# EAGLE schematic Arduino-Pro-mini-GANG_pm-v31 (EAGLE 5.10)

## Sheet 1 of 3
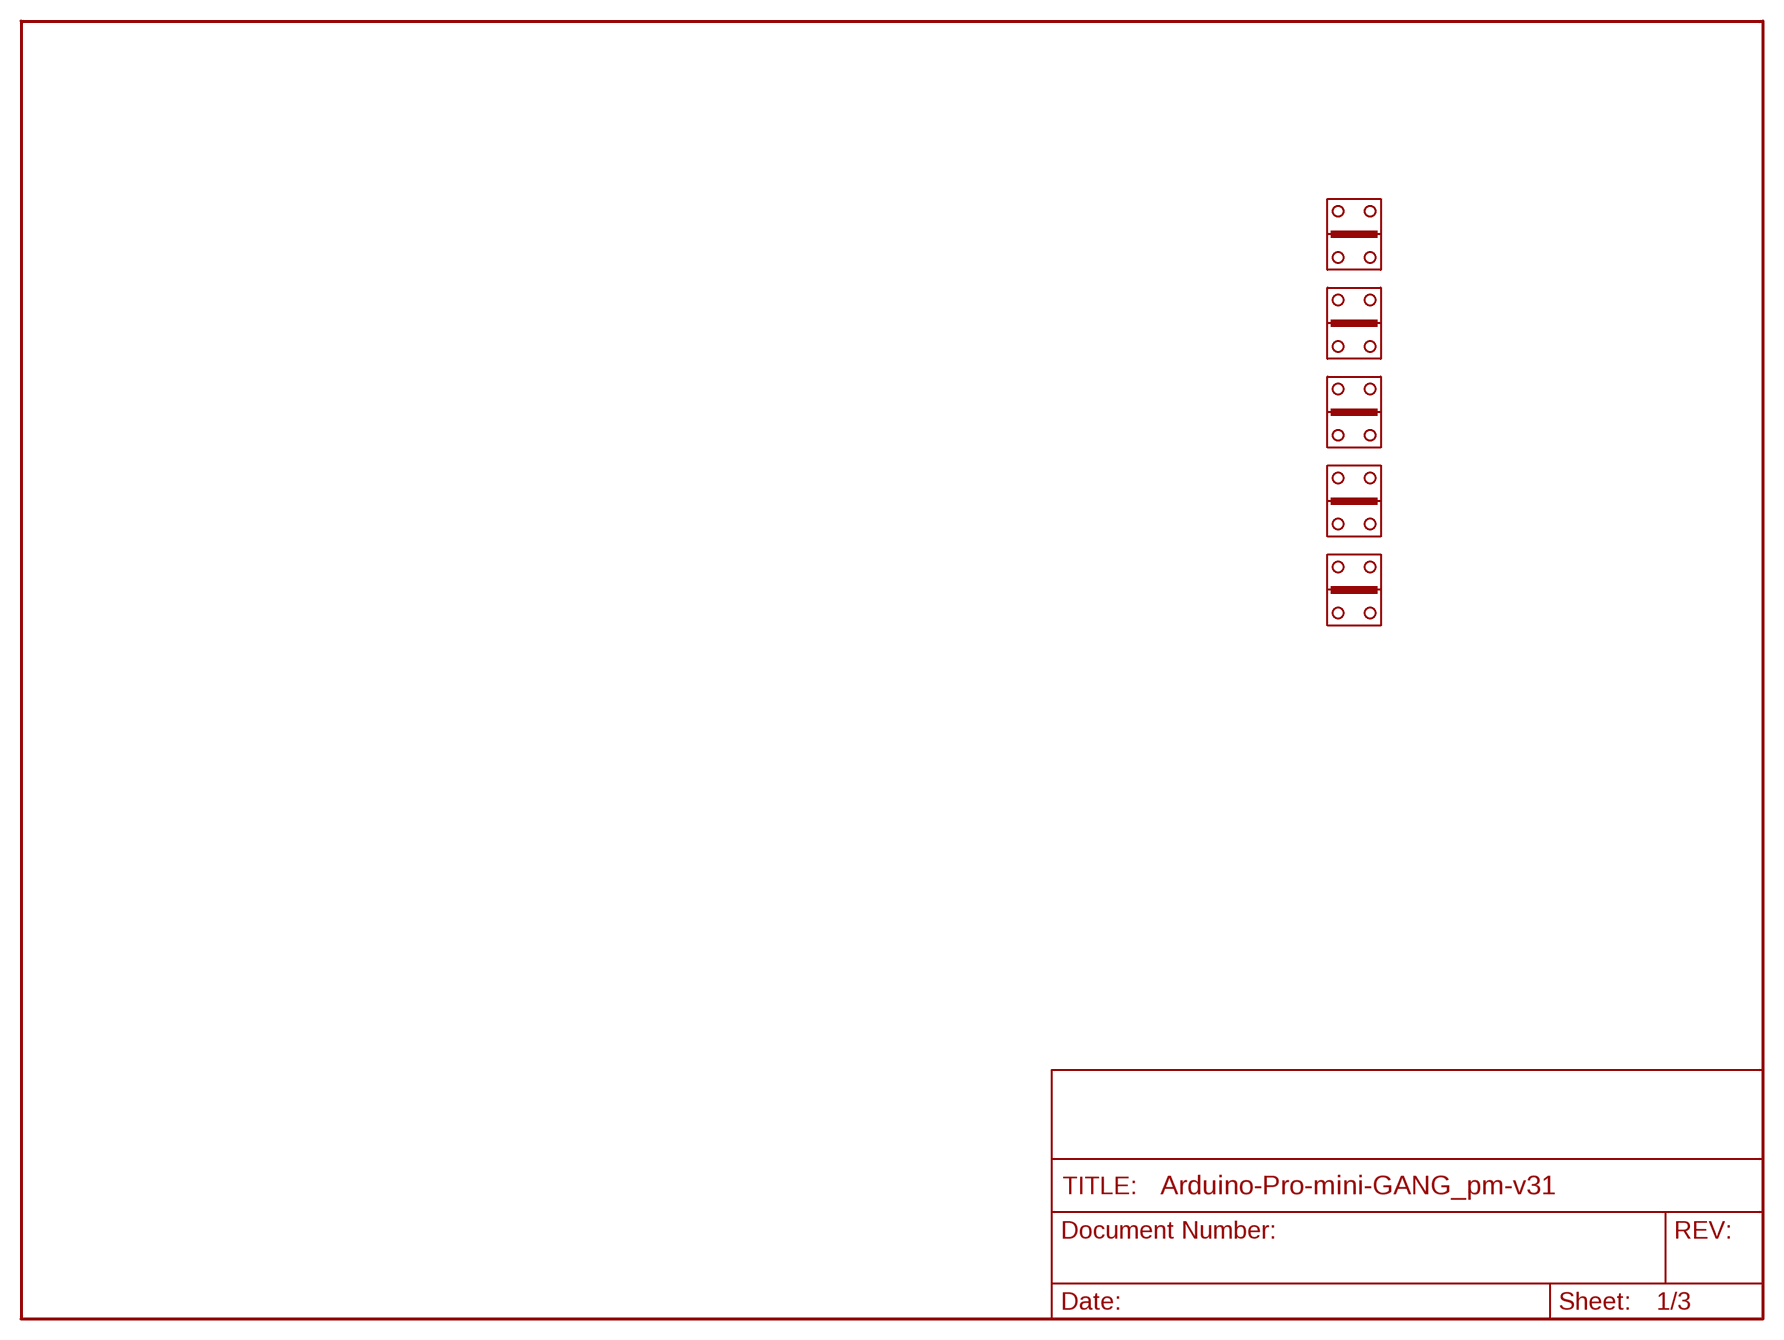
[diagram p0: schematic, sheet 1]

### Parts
U$4  GOLD_HINDGESTANDARD  [GOLD_HINDGE]
U$5  GOLD_HINDGESTANDARD  [GOLD_HINDGE]
U$6  GOLD_HINDGESTANDARD  [GOLD_HINDGE]
U$7  GOLD_HINDGESTANDARD  [GOLD_HINDGE]
U$8  GOLD_HINDGESTANDARD  [GOLD_HINDGE]

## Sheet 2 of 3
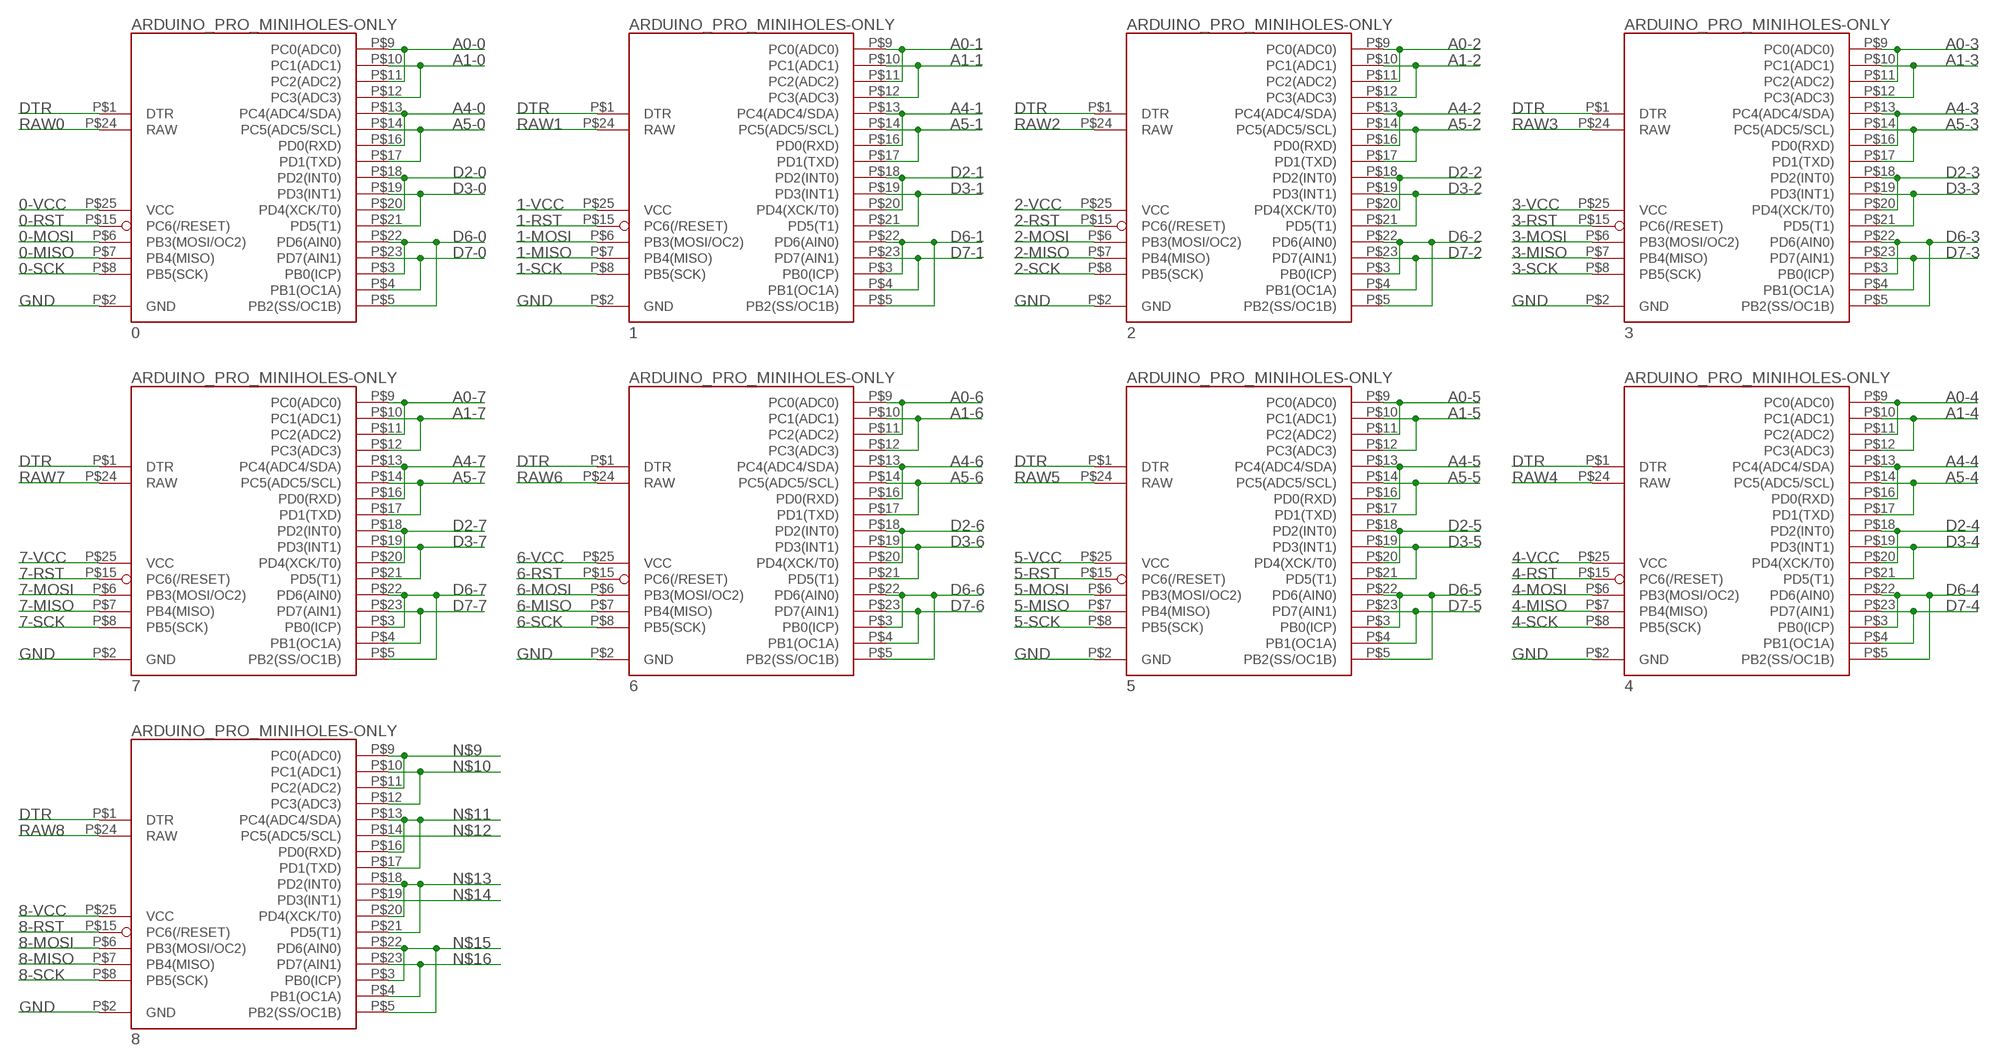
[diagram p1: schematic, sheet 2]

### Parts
0  ARDUINO_PRO_MINIHOLES-ONLY  ARDUINO_PRO_MINIPM  [ARDUINO_PRO_MINI_PM-V2]
1  ARDUINO_PRO_MINIHOLES-ONLY  ARDUINO_PRO_MINIPM  [ARDUINO_PRO_MINI_PM-V2]
2  ARDUINO_PRO_MINIHOLES-ONLY  ARDUINO_PRO_MINIPM  [ARDUINO_PRO_MINI_PM-V2]
3  ARDUINO_PRO_MINIHOLES-ONLY  ARDUINO_PRO_MINIPM  [ARDUINO_PRO_MINI_PM-V2]
4  ARDUINO_PRO_MINIHOLES-ONLY  ARDUINO_PRO_MINIPM  [ARDUINO_PRO_MINI_PM-V2]
5  ARDUINO_PRO_MINIHOLES-ONLY  ARDUINO_PRO_MINIPM  [ARDUINO_PRO_MINI_PM-V2]
6  ARDUINO_PRO_MINIHOLES-ONLY  ARDUINO_PRO_MINIPM  [ARDUINO_PRO_MINI_PM-V2]
7  ARDUINO_PRO_MINIHOLES-ONLY  ARDUINO_PRO_MINIPM  [ARDUINO_PRO_MINI_PM-V2]
8  ARDUINO_PRO_MINIHOLES-ONLY  ARDUINO_PRO_MINIPM  [ARDUINO_PRO_MINI_PM-V2]

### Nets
0-MISO: 0.P$7(PB4(MISO))
0-MOSI: 0.P$6(PB3(MOSI/OC2))
0-RST: 0.P$15(PC6(/RESET))
0-SCK: 0.P$8(PB5(SCK))
0-VCC: 0.P$25(VCC)
1-MISO: 1.P$7(PB4(MISO))
1-MOSI: 1.P$6(PB3(MOSI/OC2))
1-RST: 1.P$15(PC6(/RESET))
1-SCK: 1.P$8(PB5(SCK))
1-VCC: 1.P$25(VCC)
2-MISO: 2.P$7(PB4(MISO))
2-MOSI: 2.P$6(PB3(MOSI/OC2))
2-RST: 2.P$15(PC6(/RESET))
2-SCK: 2.P$8(PB5(SCK))
2-VCC: 2.P$25(VCC)
3-MISO: 3.P$7(PB4(MISO))
3-MOSI: 3.P$6(PB3(MOSI/OC2))
3-RST: 3.P$15(PC6(/RESET))
3-SCK: 3.P$8(PB5(SCK))
3-VCC: 3.P$25(VCC)
4-MISO: 4.P$7(PB4(MISO))
4-MOSI: 4.P$6(PB3(MOSI/OC2))
4-RST: 4.P$15(PC6(/RESET))
4-SCK: 4.P$8(PB5(SCK))
4-VCC: 4.P$25(VCC)
5-MISO: 5.P$7(PB4(MISO))
5-MOSI: 5.P$6(PB3(MOSI/OC2))
5-RST: 5.P$15(PC6(/RESET))
5-SCK: 5.P$8(PB5(SCK))
5-VCC: 5.P$25(VCC)
6-MISO: 6.P$7(PB4(MISO))
6-MOSI: 6.P$6(PB3(MOSI/OC2))
6-RST: 6.P$15(PC6(/RESET))
6-SCK: 6.P$8(PB5(SCK))
6-VCC: 6.P$25(VCC)
7-MISO: 7.P$7(PB4(MISO))
7-MOSI: 7.P$6(PB3(MOSI/OC2))
7-RST: 7.P$15(PC6(/RESET))
7-SCK: 7.P$8(PB5(SCK))
7-VCC: 7.P$25(VCC)
8-MISO: 8.P$7(PB4(MISO))
8-MOSI: 8.P$6(PB3(MOSI/OC2))
8-RST: 8.P$15(PC6(/RESET))
8-SCK: 8.P$8(PB5(SCK))
8-VCC: 8.P$25(VCC)
A0-0: 0.P$9(PC0(ADC0)) 0.P$11(PC2(ADC2))
A0-1: 1.P$9(PC0(ADC0)) 1.P$11(PC2(ADC2))
A0-2: 2.P$9(PC0(ADC0)) 2.P$11(PC2(ADC2))
A0-3: 3.P$9(PC0(ADC0)) 3.P$11(PC2(ADC2))
A0-4: 4.P$9(PC0(ADC0)) 4.P$11(PC2(ADC2))
A0-5: 5.P$9(PC0(ADC0)) 5.P$11(PC2(ADC2))
A0-6: 6.P$9(PC0(ADC0)) 6.P$11(PC2(ADC2))
A0-7: 7.P$9(PC0(ADC0)) 7.P$11(PC2(ADC2))
A1-0: 0.P$10(PC1(ADC1)) 0.P$12(PC3(ADC3))
A1-1: 1.P$10(PC1(ADC1)) 1.P$12(PC3(ADC3))
A1-2: 2.P$10(PC1(ADC1)) 2.P$12(PC3(ADC3))
A1-3: 3.P$10(PC1(ADC1)) 3.P$12(PC3(ADC3))
A1-4: 4.P$10(PC1(ADC1)) 4.P$12(PC3(ADC3))
A1-5: 5.P$10(PC1(ADC1)) 5.P$12(PC3(ADC3))
A1-6: 6.P$10(PC1(ADC1)) 6.P$12(PC3(ADC3))
A1-7: 7.P$10(PC1(ADC1)) 7.P$12(PC3(ADC3))
A4-0: 0.P$13(PC4(ADC4/SDA)) 0.P$16(PD0(RXD))
A4-1: 1.P$13(PC4(ADC4/SDA)) 1.P$16(PD0(RXD))
A4-2: 2.P$13(PC4(ADC4/SDA)) 2.P$16(PD0(RXD))
A4-3: 3.P$13(PC4(ADC4/SDA)) 3.P$16(PD0(RXD))
A4-4: 4.P$13(PC4(ADC4/SDA)) 4.P$16(PD0(RXD))
A4-5: 5.P$13(PC4(ADC4/SDA)) 5.P$16(PD0(RXD))
A4-6: 6.P$13(PC4(ADC4/SDA)) 6.P$16(PD0(RXD))
A4-7: 7.P$13(PC4(ADC4/SDA)) 7.P$16(PD0(RXD))
A5-0: 0.P$14(PC5(ADC5/SCL)) 0.P$17(PD1(TXD))
A5-1: 1.P$14(PC5(ADC5/SCL)) 1.P$17(PD1(TXD))
A5-2: 2.P$14(PC5(ADC5/SCL)) 2.P$17(PD1(TXD))
A5-3: 3.P$14(PC5(ADC5/SCL)) 3.P$17(PD1(TXD))
A5-4: 4.P$14(PC5(ADC5/SCL)) 4.P$17(PD1(TXD))
A5-5: 5.P$14(PC5(ADC5/SCL)) 5.P$17(PD1(TXD))
A5-6: 6.P$14(PC5(ADC5/SCL)) 6.P$17(PD1(TXD))
A5-7: 7.P$14(PC5(ADC5/SCL)) 7.P$17(PD1(TXD))
D2-0: 0.P$18(PD2(INT0)) 0.P$20(PD4(XCK/T0))
D2-1: 1.P$18(PD2(INT0)) 1.P$20(PD4(XCK/T0))
D2-2: 2.P$18(PD2(INT0)) 2.P$20(PD4(XCK/T0))
D2-3: 3.P$18(PD2(INT0)) 3.P$20(PD4(XCK/T0))
D2-4: 4.P$18(PD2(INT0)) 4.P$20(PD4(XCK/T0))
D2-5: 5.P$18(PD2(INT0)) 5.P$20(PD4(XCK/T0))
D2-6: 6.P$18(PD2(INT0)) 6.P$20(PD4(XCK/T0))
D2-7: 7.P$18(PD2(INT0)) 7.P$20(PD4(XCK/T0))
D3-0: 0.P$19(PD3(INT1)) 0.P$21(PD5(T1))
D3-1: 1.P$19(PD3(INT1)) 1.P$21(PD5(T1))
D3-2: 2.P$19(PD3(INT1)) 2.P$21(PD5(T1))
D3-3: 3.P$19(PD3(INT1)) 3.P$21(PD5(T1))
D3-4: 4.P$19(PD3(INT1)) 4.P$21(PD5(T1))
D3-5: 5.P$19(PD3(INT1)) 5.P$21(PD5(T1))
D3-6: 6.P$19(PD3(INT1)) 6.P$21(PD5(T1))
D3-7: 7.P$19(PD3(INT1)) 7.P$21(PD5(T1))
D6-0: 0.P$3(PB0(ICP)) 0.P$5(PB2(SS/OC1B)) 0.P$22(PD6(AIN0))
D6-1: 1.P$3(PB0(ICP)) 1.P$5(PB2(SS/OC1B)) 1.P$22(PD6(AIN0))
D6-2: 2.P$3(PB0(ICP)) 2.P$5(PB2(SS/OC1B)) 2.P$22(PD6(AIN0))
D6-3: 3.P$3(PB0(ICP)) 3.P$5(PB2(SS/OC1B)) 3.P$22(PD6(AIN0))
D6-4: 4.P$3(PB0(ICP)) 4.P$5(PB2(SS/OC1B)) 4.P$22(PD6(AIN0))
D6-5: 5.P$3(PB0(ICP)) 5.P$5(PB2(SS/OC1B)) 5.P$22(PD6(AIN0))
D6-6: 6.P$3(PB0(ICP)) 6.P$5(PB2(SS/OC1B)) 6.P$22(PD6(AIN0))
D6-7: 7.P$3(PB0(ICP)) 7.P$5(PB2(SS/OC1B)) 7.P$22(PD6(AIN0))
D7-0: 0.P$4(PB1(OC1A)) 0.P$23(PD7(AIN1))
D7-1: 1.P$4(PB1(OC1A)) 1.P$23(PD7(AIN1))
D7-2: 2.P$4(PB1(OC1A)) 2.P$23(PD7(AIN1))
D7-3: 3.P$4(PB1(OC1A)) 3.P$23(PD7(AIN1))
D7-4: 4.P$4(PB1(OC1A)) 4.P$23(PD7(AIN1))
D7-5: 5.P$4(PB1(OC1A)) 5.P$23(PD7(AIN1))
D7-6: 6.P$4(PB1(OC1A)) 6.P$23(PD7(AIN1))
D7-7: 7.P$4(PB1(OC1A)) 7.P$23(PD7(AIN1))
DTR: 0.P$1(DTR) 1.P$1(DTR) 2.P$1(DTR) 3.P$1(DTR) 4.P$1(DTR) 5.P$1(DTR) 6.P$1(DTR) 7.P$1(DTR) 8.P$1(DTR)
GND: 0.P$2(GND) 1.P$2(GND) 2.P$2(GND) 3.P$2(GND) 4.P$2(GND) 5.P$2(GND) 6.P$2(GND) 7.P$2(GND) 8.P$2(GND)
N$9: 8.P$9(PC0(ADC0)) 8.P$11(PC2(ADC2))
N$10: 8.P$10(PC1(ADC1)) 8.P$12(PC3(ADC3))
N$11: 8.P$13(PC4(ADC4/SDA)) 8.P$16(PD0(RXD)) 8.P$17(PD1(TXD))
N$12: 8.P$14(PC5(ADC5/SCL))
N$13: 8.P$18(PD2(INT0)) 8.P$20(PD4(XCK/T0)) 8.P$21(PD5(T1))
N$14: 8.P$19(PD3(INT1))
N$15: 8.P$3(PB0(ICP)) 8.P$5(PB2(SS/OC1B)) 8.P$22(PD6(AIN0))
N$16: 8.P$4(PB1(OC1A)) 8.P$23(PD7(AIN1))
RAW0: 0.P$24(RAW)
RAW1: 1.P$24(RAW)
RAW2: 2.P$24(RAW)
RAW3: 3.P$24(RAW)
RAW4: 4.P$24(RAW)
RAW5: 5.P$24(RAW)
RAW6: 6.P$24(RAW)
RAW7: 7.P$24(RAW)
RAW8: 8.P$24(RAW)

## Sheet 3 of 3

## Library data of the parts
0 1-8 = Testing:ARDUINO_PRO_MINI
U$4-U$8 = Testing:GOLD_HINDGE

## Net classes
0 Default: width 0.203 mm
1 VCC: width 0.305 mm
